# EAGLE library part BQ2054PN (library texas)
CHARGE MANAGEMENT IC
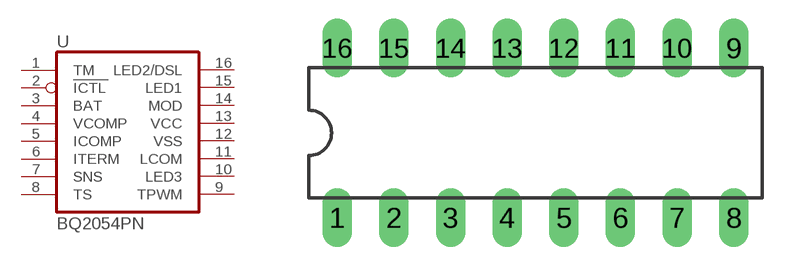
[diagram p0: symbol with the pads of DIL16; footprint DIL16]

Designator prefix U

## BQ2054PN (MF: TEXAS INSTRUMENT CONNECTORS; MPN: BQ2054PN; OC_FARNELL: 8407789; OC_NEWARK: 74C7582)  [DIL16]
1  TM  in
2  ICTL  out
3  BAT  in
4  VCOMP  in
5  ICOMP  in
6  ITERM  in
7  SNS  in
8  TS  in
9  TPWM  in
10  LED3  hiz
11  LCOM  out
12  VSS  pwr
13  VCC  pwr
14  MOD  out
15  LED1  hiz
16  LED2/DSL  hiz

## Footprint DIL16 (pad centres in mm)
Dual In Line Package
drill 0.813 long: 1 -8.89,-3.81; 2 -6.35,-3.81; 3 -3.81,-3.81; 4 -1.27,-3.81; 5 1.27,-3.81; 6 3.81,-3.81; 7 6.35,-3.81; 8 8.89,-3.81; 9 8.89,3.81; 10 6.35,3.81; 11 3.81,3.81; 12 1.27,3.81; 13 -1.27,3.81; 14 -3.81,3.81; 15 -6.35,3.81; 16 -8.89,3.81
